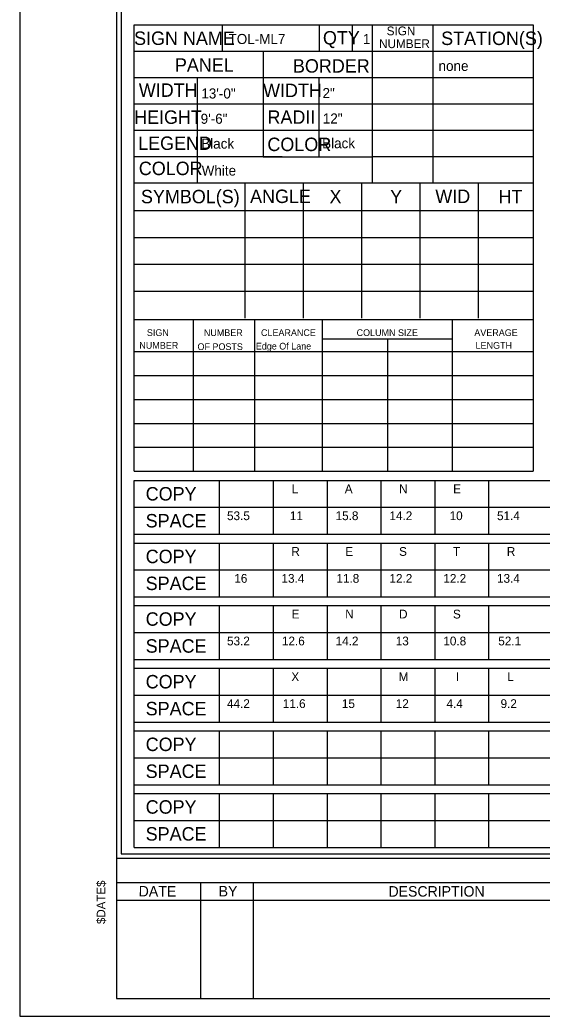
# Model space of a CAD drawing. Extents: x 122633 to 124574, y -23288 to -22025.
# Drawn here: x 122633 to 122983, y -23272 to -22604 of the extents above; entities that cross this region are included whole.
import ezdxf

# ---------------------------------------------------------------- set-up
doc = ezdxf.new("R2010")
doc.units = 0
for name, color, linetype in [('GSSign', 7, 'Continuous'), ('PlotBorder_dp', 7, 'Continuous'), ('SheetBorder_dp', 7, 'Continuous'), ('SheetLines_dp', 7, 'Continuous'), ('SheetLinesMisc2_dp', 7, 'Continuous'), ('TextMinor', 7, 'Continuous'), ('TextMisc', 7, 'Continuous')]:
    doc.layers.add(name, color=color, linetype=linetype)

msp = doc.modelspace()

# ---------------------------------------------------------------- linework, layer by layer
at = {"layer": 'PlotBorder_dp'}
msp.add_lwpolyline([(122633.11, -23271.62), (124574.11, -23271.62), (124574.11, -22024.68), (122633.11, -22024.68)], close=True, dxfattribs=at)
at = {"layer": 'SheetBorder_dp'}
for p, q in [((122697.81, -22036.45), (122697.81, -23259.86)), ((122697.81, -23165.75), (124509.41, -23165.75)), ((122697.81, -23259.86), (124509.41, -23259.86))]:
    msp.add_line(p, q, dxfattribs=at)
at = {"layer": 'SheetLines_dp'}
for p, q in [((122697.81, -23182.22), (123375.4, -23182.22)), ((122754.28, -23182.22), (122754.28, -23259.86)), ((122789.57, -23182.22), (122789.57, -23259.86)), ((122697.81, -23193.98), (123375.4, -23193.98))]:
    msp.add_line(p, q, dxfattribs=at)
at = {"layer": 'SheetLinesMisc2_dp'}
for p, q in [((122701.01, -22039.22), (122701.01, -23162.98)), ((122709.67, -22906.62), (122709.67, -22607.55)), ((122709.67, -22607.55), (122977.34, -22607.55)), ((122768.68, -22607.55), (122768.68, -22625.22)), ((122833.74, -22607.55), (122833.74, -22625.22)), ((122855.97, -22607.55), (122855.97, -22625.22)), ((122869.21, -22607.55), (122869.21, -22713.54)), ((122909.94, -22607.55), (122909.94, -22713.54)), ((122977.34, -22607.55), (122977.34, -22906.62)), ((122709.67, -22625.22), (122977.34, -22625.22)), ((122796.18, -22625.22), (122796.18, -22696.07)), ((122709.67, -22642.88), (122977.34, -22642.88)), ((122751.97, -22642.88), (122751.97, -22713.54)), ((122833.51, -22643.07), (122833.51, -22696.07)), ((122709.67, -22660.55), (122977.34, -22660.55)), ((122709.67, -22678.21), (122977.34, -22678.21)), ((122709.67, -22695.88), (122808.94, -22695.88)), ((122796.18, -22696.07), (122869.21, -22696.07)), ((122869.21, -22695.88), (122977.34, -22695.88)), ((122709.67, -22713.54), (122977.34, -22713.54)), ((122784.01, -22713.89), (122784.01, -22804.08)), ((122823.12, -22713.89), (122823.12, -22804.08)), ((122862.23, -22713.89), (122862.23, -22804.08)), ((122901.34, -22713.89), (122901.34, -22804.08)), ((122940.45, -22713.89), (122940.45, -22804.08)), ((122709.73, -22731.93), (122977.34, -22731.93)), ((122709.73, -22749.97), (122977.34, -22749.97)), ((122709.73, -22768), (122977.34, -22768)), ((122709.73, -22786.04), (122977.34, -22786.04)), ((122709.67, -22804.95), (122977.34, -22804.95)), ((122749.39, -22804.95), (122749.39, -22906.62)), ((122790.45, -22804.95), (122790.45, -22906.62)), ((122835.78, -22804.95), (122835.78, -22906.62)), ((122923.07, -22804.95), (122923.07, -22906.62)), ((122835.78, -22817.88), (122923.01, -22817.88)), ((122879.6, -22817.88), (122879.6, -22906.62)), ((122709.67, -22826.5), (122977.34, -22826.5)), ((122709.67, -22842.52), (122977.34, -22842.52)), ((122709.67, -22858.55), (122977.34, -22858.55)), ((122709.67, -22874.57), (122977.34, -22874.57)), ((122709.67, -22890.6), (122977.34, -22890.6)), ((122709.67, -22906.62), (122977.34, -22906.62)), ((122709.67, -22912.77), (123597.5, -22912.77)), ((122709.67, -23158.6), (122709.67, -22912.77)), ((122766.82, -22912.77), (122766.82, -22948.85)), ((122802.94, -22912.77), (122802.94, -22948.85)), ((122839.06, -22912.77), (122839.06, -22948.85)), ((122875.17, -22912.77), (122875.17, -22948.85)), ((122911.28, -22912.77), (122911.28, -22948.85)), ((122947.4, -22912.77), (122947.4, -22948.85)), ((122709.67, -22930.8), (123597.5, -22930.8)), ((122709.67, -22948.85), (123597.5, -22948.85)), ((122709.67, -22954.73), (123597.5, -22954.73)), ((122766.82, -22954.73), (122766.82, -22990.8)), ((122802.94, -22954.73), (122802.94, -22990.8)), ((122839.06, -22954.73), (122839.06, -22990.8)), ((122875.17, -22954.73), (122875.17, -22990.8)), ((122911.28, -22954.73), (122911.28, -22990.8)), ((122947.4, -22954.73), (122947.4, -22990.8)), ((122709.67, -22972.77), (123597.5, -22972.77)), ((122709.67, -22990.8), (123597.5, -22990.8)), ((122709.67, -22996.68), (123597.5, -22996.68)), ((122766.82, -22996.68), (122766.82, -23032.75)), ((122802.94, -22996.68), (122802.94, -23032.75)), ((122839.06, -22996.68), (122839.06, -23032.75)), ((122875.17, -22996.68), (122875.17, -23032.75)), ((122911.28, -22996.68), (122911.28, -23032.75)), ((122947.4, -22996.68), (122947.4, -23032.75)), ((122709.67, -23014.71), (123597.5, -23014.71)), ((122709.67, -23032.75), (123597.5, -23032.75)), ((122709.67, -23038.63), (123597.5, -23038.63)), ((122766.82, -23038.63), (122766.82, -23074.71)), ((122802.94, -23038.63), (122802.94, -23074.71)), ((122839.06, -23038.63), (122839.06, -23074.71)), ((122875.17, -23038.63), (122875.17, -23074.71)), ((122911.28, -23038.63), (122911.28, -23074.71)), ((122947.4, -23038.63), (122947.4, -23074.71)), ((122709.67, -23056.66), (123597.5, -23056.66)), ((122709.67, -23074.71), (123597.5, -23074.71)), ((122709.67, -23080.59), (123597.5, -23080.59)), ((122766.82, -23080.59), (122766.82, -23116.66)), ((122802.94, -23080.59), (122802.94, -23116.66)), ((122839.06, -23080.59), (122839.06, -23116.66)), ((122875.17, -23080.59), (122875.17, -23116.66)), ((122911.28, -23080.59), (122911.28, -23116.66)), ((122947.4, -23080.59), (122947.4, -23116.66)), ((122709.67, -23098.63), (123597.5, -23098.63)), ((122709.67, -23116.66), (123597.5, -23116.66)), ((122709.67, -23122.54), (123597.5, -23122.54)), ((122766.82, -23122.54), (122766.82, -23158.6)), ((122802.94, -23122.54), (122802.94, -23158.6)), ((122839.06, -23122.54), (122839.06, -23158.6)), ((122875.17, -23122.54), (122875.17, -23158.6)), ((122911.28, -23122.54), (122911.28, -23158.6)), ((122947.4, -23122.54), (122947.4, -23158.6)), ((122709.67, -23140.57), (123597.5, -23140.57)), ((122709.67, -23158.6), (123597.5, -23158.6)), ((122701.01, -23162.98), (124506.26, -23162.98))]:
    msp.add_line(p, q, dxfattribs=at)

# ---------------------------------------------------------------- texts
at = {"layer": 'GSSign'}
for s, height, p in [('TOL-ML7', 6.749, (122773.03, -22620.47)), ('1', 6.75, (122863.12, -22620.48)), ('none', 6.749, (122913.83, -22638.49)), ('13\'-0"', 6.749, (122754.78, -22656.95)), ('2"', 6.749, (122836.04, -22656.7)), ('9\'-6"', 6.749, (122754.32, -22673.91)), ('12"', 6.749, (122836.22, -22673.72)), ('Black', 6.749, (122754.7, -22690.55)), ('Black', 6.749, (122835.77, -22690.29)), ('White', 6.749, (122755, -22708.59)), ('L', 5.88, (122815.4, -22921.37)), ('A', 5.88, (122850.96, -22921.37)), ('N', 5.88, (122887.36, -22921.37)), ('E', 5.88, (122923.63, -22921.37)), ('53.5', 5.882, (122771.99, -22939.4)), ('11', 5.882, (122814.14, -22939.4)), ('15.8', 5.882, (122844.8, -22939.4)), ('14.2', 5.882, (122880.92, -22939.4)), ('10', 5.882, (122921.25, -22939.4)), ('51.4', 5.882, (122953.03, -22939.4)), ('R', 5.88, (122815.12, -22963.32)), ('E', 5.88, (122851.38, -22963.32)), ('S', 5.88, (122887.36, -22963.32)), ('T', 5.88, (122923.49, -22963.32)), ('R', 5.88, (122959.61, -22963.32)), ('16', 5.882, (122776.89, -22981.36)), ('13.4', 5.882, (122808.53, -22981.36)), ('11.8', 5.882, (122845.36, -22981.36)), ('12.2', 5.882, (122880.92, -22981.36)), ('12.2', 5.882, (122917.05, -22981.36)), ('13.4', 5.882, (122953.03, -22981.36)), ('E', 5.88, (122815.26, -23005.28)), ('N', 5.88, (122851.24, -23005.28)), ('D', 5.88, (122887.36, -23005.28)), ('S', 5.88, (122923.49, -23005.28)), ('53.2', 5.882, (122771.99, -23023.31)), ('12.6', 5.882, (122808.81, -23023.31)), ('14.2', 5.882, (122844.8, -23023.31)), ('13', 5.882, (122885.12, -23023.31)), ('10.8', 5.882, (122917.05, -23023.31)), ('52.1', 5.882, (122953.87, -23023.31)), ('X', 5.88, (122815.12, -23047.23)), ('M', 5.88, (122887.08, -23047.23)), ('I', 5.88, (122925.45, -23047.23)), ('L', 5.88, (122959.89, -23047.23)), ('44.2', 5.882, (122771.99, -23065.27)), ('11.6', 5.882, (122809.37, -23065.27)), ('15', 5.882, (122849, -23065.27)), ('12', 5.882, (122885.12, -23065.27)), ('4.4', 5.882, (122919.15, -23065.27)), ('9.2', 5.882, (122955.41, -23065.27))]:
    msp.add_text(s, height=height, dxfattribs=at).set_placement(p)
at = {"layer": 'TextMinor'}
for s, height, p in [('SIGN NAME', 8.999, (122709.67, -22621.08)), ('QTY', 8.999, (122836.3, -22620.78)), ('SIGN', 5.882, (122879.04, -22614.63)), ('STATION(S)', 8.999, (122915.56, -22621.13)), ('NUMBER', 5.882, (122873.93, -22623.19)), ('PANEL', 8.999, (122737.04, -22639.02)), ('BORDER', 8.999, (122816.19, -22639.63)), ('WIDTH', 8.999, (122712.85, -22655.84)), ('WIDTH', 8.999, (122796.18, -22656.02)), ('HEIGHT', 8.999, (122709.67, -22673.95)), ('RADII', 8.999, (122799.13, -22673.92)), ('LEGEND', 8.999, (122712.38, -22691.42)), ('COLOR', 8.999, (122799.07, -22692.18)), ('COLOR', 8.999, (122712.85, -22708.27)), ('SYMBOL(S)', 8.999, (122714.28, -22727.16)), ('ANGLE', 8.999, (122787.45, -22726.97)), ('X', 9, (122840.72, -22727.16)), ('Y', 9, (122881.39, -22727.16)), ('WID', 8.999, (122911.67, -22726.97)), ('HT', 8.999, (122954.07, -22727.14)), ('SIGN', 4.5, (122718.25, -22816.04)), ('NUMBER', 4.5, (122756.45, -22816.1)), ('CLEARANCE', 4.5, (122794.77, -22816.07)), ('COLUMN SIZE', 4.4996, (122858.89, -22816.07)), ('AVERAGE', 4.5, (122937.81, -22816.07)), ('NUMBER', 4.5, (122713.21, -22824.6)), ('OF POSTS', 4.5, (122752.2, -22825.45)), ('Edge Of Lane', 4.4996, (122791.3, -22825.12)), ('LENGTH', 4.5, (122938.66, -22824.6)), ('COPY', 8.999, (122717.46, -22926.26)), ('SPACE', 8.999, (122717.46, -22944.3)), ('COPY', 8.999, (122717.46, -22968.23)), ('SPACE', 8.999, (122717.46, -22986.26)), ('COPY', 8.999, (122717.46, -23010.16)), ('SPACE', 8.999, (122717.46, -23028.2)), ('COPY', 8.999, (122717.46, -23052.13)), ('SPACE', 8.999, (122717.46, -23070.16)), ('COPY', 8.999, (122717.46, -23094.09)), ('SPACE', 8.999, (122717.46, -23112.12)), ('COPY', 8.999, (122717.46, -23136.04)), ('SPACE', 8.999, (122717.46, -23154.06))]:
    msp.add_text(s, height=height, dxfattribs=at).set_placement(p)
msp.add_text('$DATE$', height=5.764, rotation=90, dxfattribs=at).set_placement((122690.4, -23209.96))
at = {"layer": 'TextMisc'}
for s, height, rotation, p in [('DATE', 7.058, 359.86925, (122712.75, -23191.51)), ('DESCRIPTION', 7.0567, 0.04975, (122880.27, -23191.63))]:
    msp.add_text(s, height=height, rotation=rotation, dxfattribs=at).set_placement(p)
msp.add_text('BY', height=7.058, dxfattribs=at).set_placement((122766.39, -23191.51))

doc.saveas('drawing.dxf')
